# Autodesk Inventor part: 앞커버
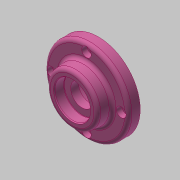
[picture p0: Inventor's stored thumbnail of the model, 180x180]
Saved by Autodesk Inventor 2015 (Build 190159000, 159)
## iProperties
Created: 2017-08
Part Number: 앞커버
Material: 알루미늄 6061
Document SubType Name: Modeling
Designer: mduedu
Density: 2.71 g/cm^3
Appearance: 분홍색
Mass: 117.255 g
Surface Area: 148.119 cm^2
Volume: 43.2676 cm^3
Author: mduedu
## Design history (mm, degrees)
sketch "스케치1"
  geometry: C1 r 35 at (0, 0); 1 further point
  constraints: 1 centre point, 1 coincident
  dimensions: "d0" = 70 diameter of C1
extrude "돌출1" new body sketch "스케치1" distance "d1" = 10; taper "d2" = 0 deg
sketch "스케치2"
  geometry: C1 r 22 at (0, 0); 1 further point
  constraints: 1 centre point, 1 coincident
  dimensions: "d3" = 44 diameter of C1
node "작업 평면1"
sketch "스케치3"
  geometry: C1 r 21 at (0, 0); 1 further point
  constraints: 1 centre point, 1 coincident
  dimensions: "d5" = 42 diameter of C1
feature "로프트1" sketch "스케치3" dims "d6" = 0, "d7" = 90 deg, "d8" = 0, "d9" = 90 deg
sketch "스케치4"
  geometry: C1 r 24 at (0, 0); 1 further point
  constraints: 1 centre point, 1 coincident
  dimensions: "d86" = 48 diameter of C1
extrude "돌출2" join sketch "스케치4" distance "d10" = 8; taper "d11" = 0 deg
hole "구멍1" diameter "d14" = 40; stored, may be unused: countersink angle "d18" = 90 deg, drill point angle "d20" = 0 deg; dims "d15" = 6, "d16" = 4, "d17" = 2, "d19" = 12, "d87" = 10, "d88" = 10
hole "구멍2" diameter "d23" = 34; stored, may be unused: countersink angle "d27" = 90 deg, drill point angle "d29" = 0 deg; dims "d21" = 10, "d22" = 10, "d24" = 6, "d25" = 4, "d26" = 2, "d28" = 3
hole "구멍3" diameter "d32" = 19; stored, may be unused: countersink angle "d36" = 90 deg, drill point angle "d38" = 0 deg; dims "d30" = 10, "d31" = 10, "d33" = 6, "d34" = 4, "d35" = 2, "d37" = 3
chamfer "모따기1" distance "d39" = 1; stored, may be unused: second distance "d40" = 2, angle "d41" = 45 deg
sketch "스케치5"
  geometry: C1 r 15 at (0, 0); 1 further point
  constraints: 1 centre point, 1 coincident
  dimensions: "d42" = 30 diameter of C1
extrude "돌출3" cut sketch "스케치5" distance "d43" = 8.3; taper "d44" = 0 deg
chamfer "모따기2" distance "d47" = 0.8; stored, may be unused: second distance "d48" = 2, angle "d49" = 30 deg
fillet "모깎기1" dims "d50" = 0.3
fillet "모깎기2" dims "d51" = 0.3
fillet "모깎기3" dims "d52" = 3
sketch "스케치6" dims "d53" = 58
  geometry: 6 further points
  constraints: 2 vertical alignment, 1 coincident, 7 other
  dimensions: "d56" = 360 deg dimension on point (0, 0) point (0, 29) (derived)
sketch "스케치9" dims "d85" = 58 (derived)
  geometry: 6 further points
  constraints: 1 coincident, 1 vertical alignment, 6 other
hole "구멍6" sketch "스케치9" at (-29, 0), (0, -29), (29, 0), (0, 29) diameter "d72" = 4.5; stored, may be unused: countersink angle "d76" = 90 deg, drill point angle "d78" = 0 deg; dims "d73" = 6, "d74" = 8, "d75" = 4.6, "d77" = 8
fillet "모깎기4" dims "d79" = 3
fillet "모깎기5" dims "d80" = 3
fillet "모깎기6" dims "d81" = 3
node "솔리드1"
other parameters: "d4" = 12
